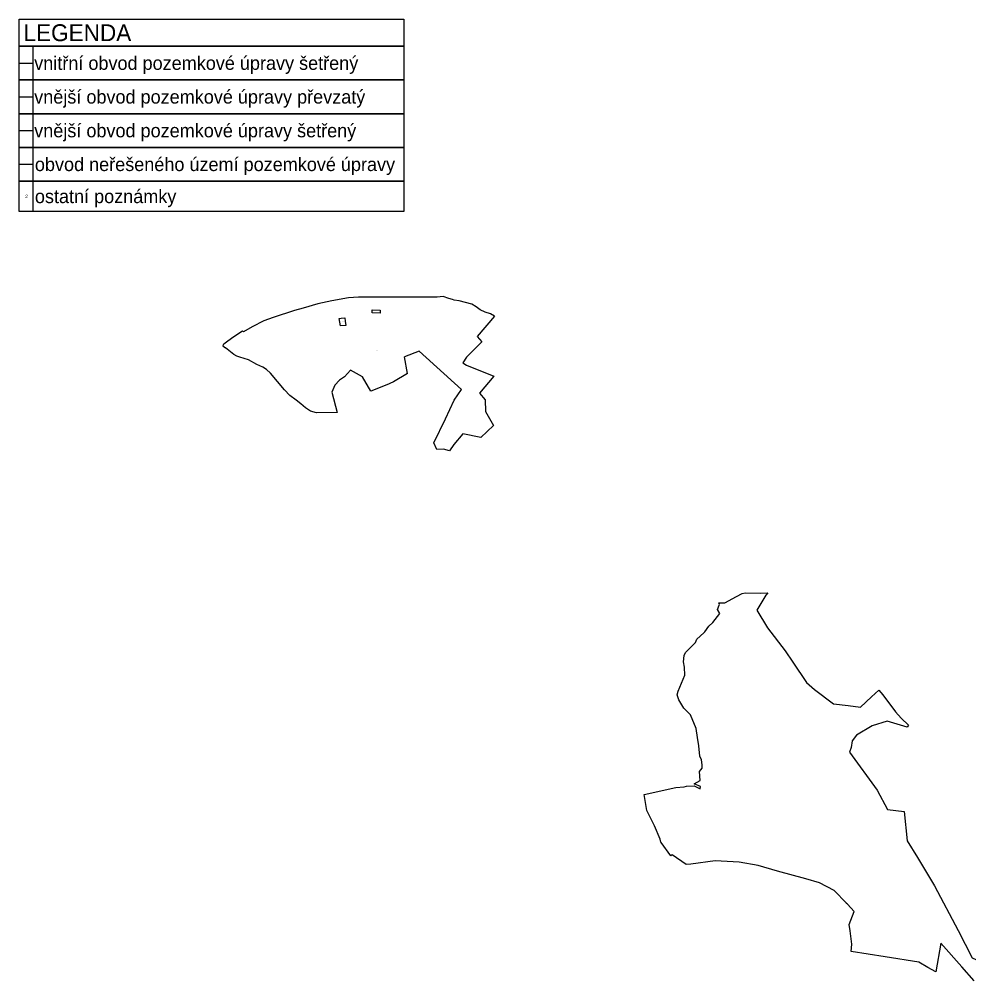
# Model space of a CAD drawing. Extents: x -786335 to -780566, y -1186928 to -1182998.
# Drawn here: x -786335 to -783521, y -1185848 to -1182998 of the extents above; entities that cross this region are included whole.
import ezdxf

# ---------------------------------------------------------------- set-up
doc = ezdxf.new("R2010")
doc.units = 0
for name, color, linetype in [('GR_MER', 7, 'Continuous'), ('LEGENDA', 7, 'Continuous'), ('Level 255', 7, 'Continuous'), ('NERES_SET', 7, 'Continuous'), ('OVNE_PRE', 7, 'Continuous'), ('OVNE_SET', 7, 'Continuous'), ('POZN', 7, 'Continuous')]:
    doc.layers.add(name, color=color, linetype=linetype)

msp = doc.modelspace()

# ---------------------------------------------------------------- linework, layer by layer
at = {"layer": 'GR_MER'}
for p, q in [((-786294.8, -1183078.1), (-786294.8, -1183178.1)), ((-786294.8, -1183178.1), (-786294.8, -1183278.1)), ((-786294.8, -1183278.1), (-786294.8, -1183378.1)), ((-786294.8, -1183378.1), (-786294.8, -1183478.1)), ((-786294.8, -1183478.1), (-786294.8, -1183568.1))]:
    msp.add_line(p, q, dxfattribs=at)
at = {"layer": 'LEGENDA'}
for p, q in [((-786333.8, -1183128.1), (-786295.8, -1183128.1)), ((-786333.8, -1183228.1), (-786295.8, -1183228.1)), ((-786333.8, -1183328.1), (-786295.8, -1183328.1)), ((-786333.8, -1183428.1), (-786295.8, -1183428.1))]:
    msp.add_line(p, q, dxfattribs=at)
at = {"layer": 'Level 255'}
for points in [[(-786334.8, -1182998.1), (-785194.8, -1182998.1), (-785194.8, -1183078.1), (-786334.8, -1183078.1), (-786334.8, -1182998.1)], [(-786334.8, -1183078.1), (-786294.8, -1183078.1), (-785194.8, -1183078.1), (-785194.8, -1183178.1), (-786294.8, -1183178.1), (-786334.8, -1183178.1), (-786334.8, -1183078.1)], [(-786334.8, -1183178.1), (-786294.8, -1183178.1), (-785194.8, -1183178.1), (-785194.8, -1183278.1), (-786294.8, -1183278.1), (-786334.8, -1183278.1), (-786334.8, -1183178.1)], [(-786334.8, -1183278.1), (-786294.8, -1183278.1), (-785194.8, -1183278.1), (-785194.8, -1183378.1), (-786294.8, -1183378.1), (-786334.8, -1183378.1), (-786334.8, -1183278.1)], [(-786334.8, -1183378.1), (-786294.8, -1183378.1), (-785194.8, -1183378.1), (-785194.8, -1183478.1), (-786294.8, -1183478.1), (-786334.8, -1183478.1), (-786334.8, -1183378.1)], [(-786334.8, -1183478.1), (-786294.8, -1183478.1), (-785194.8, -1183478.1), (-785194.8, -1183568.1), (-786294.8, -1183568.1), (-786334.8, -1183568.1), (-786334.8, -1183478.1)]]:
    msp.add_lwpolyline(points, dxfattribs=at)
at = {"layer": 'NERES_SET'}
for points in [[(-785289.2, -1183868.6), (-785289.1, -1183859.8), (-785265.3, -1183860.1), (-785265.2, -1183869.2), (-785289.2, -1183868.6)], [(-785383.1, -1183906.5), (-785386.5, -1183884.6), (-785381.1, -1183884.2), (-785370, -1183883.1), (-785369.1, -1183893.2), (-785367, -1183905.5), (-785383.1, -1183906.5)]]:
    msp.add_lwpolyline(points, dxfattribs=at)
at = {"layer": 'OVNE_PRE'}
for points in [[(-785096.7, -1183822), (-785230.8, -1183821.8), (-785329.2, -1183821.9), (-785359.2, -1183824.2), (-785408.3, -1183832.3), (-785449.5, -1183841.3), (-785493.6, -1183854), (-785519.4, -1183861.5), (-785582.5, -1183882.1), (-785609.7, -1183892.4), (-785644.7, -1183909.5), (-785670.5, -1183924.6), (-785673, -1183922.3), (-785701.8, -1183941.2), (-785724.3, -1183958.4), (-785729.2, -1183962.2), (-785730.8, -1183963.4), (-785731.8, -1183965.6)], [(-784926.6, -1183877.8), (-784938.1, -1183871.4), (-784953.9, -1183866.3), (-784968.7, -1183858.9), (-784980.6, -1183850.4), (-784993.2, -1183842.7), (-785030.7, -1183832.2), (-785045.5, -1183831), (-785051.2, -1183828.4), (-785061.2, -1183825.3), (-785078.7, -1183820.1), (-785096.7, -1183822)], [(-784261.8, -1184727.9), (-784243.5, -1184727.6), (-784209.2, -1184709.1), (-784192.6, -1184699.7), (-784183.6, -1184698.4), (-784138.3, -1184699), (-784116.6, -1184697.7)], [(-784357.9, -1185503.6), (-784399.7, -1185474.7), (-784404.2, -1185477.1), (-784432.6, -1185438.3), (-784433.7, -1185436.7)], [(-783505, -1185847.8), (-783541.2, -1185806.8), (-783603.8, -1185736), (-783618, -1185821), (-783641.6, -1185808), (-783668.6, -1185793.1), (-783768.9, -1185777.3), (-783869.2, -1185761.5), (-783867.1, -1185739.5), (-783872.5, -1185699.4), (-783875.1, -1185680.6), (-783860, -1185642.3), (-783880.5, -1185621), (-783882.7, -1185618.7), (-783883.5, -1185617.8), (-783919.2, -1185580.7), (-783963, -1185557.1), (-784003.6, -1185545.2), (-784087.3, -1185523.4), (-784145.2, -1185506.1), (-784201.4, -1185496.3), (-784272.4, -1185492.3), (-784344.2, -1185501.8), (-784357.9, -1185503.6)]]:
    msp.add_lwpolyline(points, dxfattribs=at)
at = {"layer": 'OVNE_SET'}
for p, q in [((-785731.8, -1183965.6), (-785723.1, -1183972.1)), ((-785184.5, -1184048.1), (-785193.3, -1183999))]:
    msp.add_line(p, q, dxfattribs=at)
for points in [[(-784926.6, -1183877.8), (-784978.1, -1183938.4), (-784964.2, -1183954), (-785009.7, -1183999.3), (-785020.1, -1184016.1), (-785009.4, -1184023.6), (-784928.2, -1184056.2), (-784970.7, -1184106.6), (-784954.2, -1184126.2), (-784953.1, -1184160.5), (-784929.5, -1184202.1), (-784967.3, -1184237.7), (-785019.7, -1184227.1), (-785047.2, -1184258.2), (-785060.1, -1184276.8), (-785077.1, -1184272.7), (-785097.6, -1184272.8), (-785106.1, -1184253.2), (-785071.8, -1184182.3), (-785045.6, -1184127.2), (-785024.5, -1184095.2), (-785149.6, -1183982), (-785193.3, -1183999)], [(-785353.4, -1184037.7), (-785371.1, -1184057.9), (-785385.2, -1184067.7), (-785399.5, -1184083), (-785408.1, -1184103.5), (-785392.4, -1184163.7), (-785453.8, -1184164.9), (-785471.6, -1184159.2), (-785486.6, -1184150.1), (-785500.4, -1184137.7), (-785514.3, -1184127), (-785533.1, -1184113.7), (-785548.3, -1184096.4), (-785590.5, -1184047.1), (-785602.1, -1184036.6), (-785613.1, -1184029.7), (-785630.3, -1184020.9), (-785655.8, -1184007.7), (-785668.1, -1184003.2), (-785681.2, -1184000.1), (-785690.3, -1183996.8), (-785699.3, -1183991.3), (-785723.1, -1183972.1)], [(-785184.5, -1184048.1), (-785225.2, -1184072.7), (-785236.4, -1184077.5), (-785238.7, -1184078.5), (-785259.8, -1184087.5), (-785293.2, -1184100.3), (-785317.7, -1184057.6), (-785353.4, -1184037.7)], [(-784116.6, -1184697.7), (-784121.7, -1184705.3), (-784149.2, -1184749.6), (-784117.7, -1184801.3), (-784064.7, -1184870.3), (-784041.9, -1184903.4), (-784001.2, -1184963.7), (-783977.7, -1184984.7), (-783922.1, -1185026.8), (-783877.7, -1185031.8), (-783841.6, -1185037.3), (-783809.2, -1185006.2), (-783787.2, -1184986.5), (-783775.6, -1185000.4), (-783737.4, -1185050.7), (-783721.4, -1185069.1), (-783698.9, -1185090.3), (-783703.2, -1185096.3), (-783762.4, -1185078.5), (-783807.3, -1185092.1), (-783853.9, -1185119.7), (-783866, -1185136.8), (-783869.5, -1185156.1)], [(-784433.7, -1185436.7), (-784435.6, -1185428.1), (-784452.5, -1185388.8), (-784474.8, -1185343.3), (-784482.6, -1185295.6), (-784388.6, -1185275.4), (-784364.2, -1185273.4), (-784357.6, -1185270.6), (-784334.3, -1185270.5), (-784316.5, -1185278.7), (-784315.6, -1185272.5), (-784334.2, -1185264), (-784316.8, -1185253.9), (-784318.8, -1185227.2), (-784311.2, -1185217.9), (-784310.4, -1185207.8), (-784312.6, -1185193.2), (-784317.9, -1185181.8), (-784321, -1185151.5), (-784325.1, -1185126.7), (-784328.7, -1185099.9), (-784345, -1185060.1), (-784365.1, -1185039.6), (-784380, -1185015), (-784384.5, -1185000.8), (-784382.3, -1184989.8), (-784362.4, -1184942), (-784362.9, -1184918.3), (-784366.2, -1184902.1), (-784364, -1184884), (-784360.1, -1184875.1), (-784330.8, -1184845.4), (-784326.8, -1184835.8), (-784306.4, -1184816.8), (-784302.5, -1184813.3), (-784291.3, -1184797.3), (-784278.8, -1184785.8), (-784258.4, -1184759.8), (-784265.8, -1184747), (-784260.9, -1184735.1), (-784259.8, -1184732.3), (-784261.8, -1184727.9)], [(-783869.5, -1185156.1), (-783874.4, -1185170.5), (-783792.3, -1185282.7), (-783761.7, -1185340.4), (-783711.8, -1185346.4), (-783703.5, -1185432.9), (-783672.7, -1185482.5), (-783622, -1185566.7), (-783551.8, -1185699.2), (-783511, -1185779.4), (-783482.5, -1185793.1), (-783408.9, -1185842.2)]]:
    msp.add_lwpolyline(points, dxfattribs=at)

# ---------------------------------------------------------------- texts
at = {"layer": 'Level 255'}
for s, height, p in [('LEGENDA', 50, (-786322.3, -1183063.1)), ('vnitřní obvod pozemkové úpravy šetřený', 40, (-786290.4, -1183148.1)), ('vnější obvod pozemkové úpravy převzatý', 40, (-786290.4, -1183248.1)), ('vnější obvod pozemkové úpravy šetřený', 40, (-786290.4, -1183348.1)), ('obvod neřešeného území pozemkové úpravy', 40, (-786288.4, -1183448.1)), ('ostatní poznámky', 40, (-786288.4, -1183543.1)), ('2', 10, (-786317.1, -1183528.1))]:
    msp.add_text(s, height=height, dxfattribs=at).set_placement(p)
at = {"layer": 'POZN'}
for s, p in [('1', (-785277.6, -1183864.8)), ('1', (-785376.2, -1183894.1)), ('2', (-785275.2, -1183982.4))]:
    msp.add_text(s, height=2, dxfattribs=at).set_placement(p)

doc.saveas('drawing.dxf')
